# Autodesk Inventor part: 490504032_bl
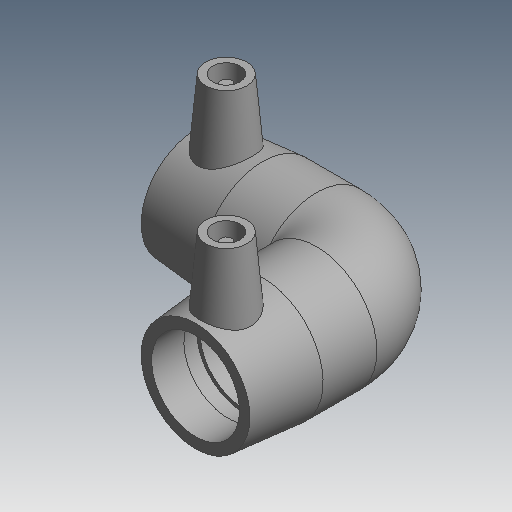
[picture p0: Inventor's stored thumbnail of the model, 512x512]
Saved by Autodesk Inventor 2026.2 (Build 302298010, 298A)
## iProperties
Created: 2017-06
Part Number: 490504032_bl
Material: Generic
Description: PLASSON 90° ELBOW 32
Document SubType Name: Modeling
Designer: KIM
Mass: 55.0731 g
Surface Area: 148.067 cm^2
Volume: 55.0731 cm^3
Density: 1 g/cm^3
Appearance: Default
Author: KIM
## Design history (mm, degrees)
derived "490504 -20-75.ipt"
feature "Solid1::490504 -20-75.ipt" dims "ScaleForDerivedMember" = 10
tag "TaggingFeature1"
body "Solid1"
other parameters: "d2" = 44 [user parameter], "d4" = 24.41176 [user parameter], "d5" = 39.6 [user parameter], "d8" = 168 deg [user parameter], "d10" = 17.6 [user parameter], "d11" = 5.86667 [user parameter], "d14" = 17.6296 [user parameter], "d18" = 32 [user parameter], "d19" = 3.52592 [user parameter], "d20" = 168 deg [user parameter], "d22" = 40.48 [user parameter], "d23" = 44 [user parameter], "d24" = 39.2656 [user parameter], "d29" = 43 [user parameter], "d30" = 15 [user parameter], "d31" = 49.8 [user parameter], "d34" = 5 deg [user parameter], "d35" = 15 [user parameter], "d39" = 5 deg [user parameter], "d41" = 4 [user parameter], "d42" = 14 [user parameter], "d43" = 0 [user parameter], "d45" = 4 [user parameter], "d46" = 14 [user parameter], "d47" = 0 [user parameter], "d49" = 32 [user parameter], "d50" = 27.2 [user parameter], "d51" = 17.6 [user parameter], "d52" = 44 [user parameter], "d54" = 90 deg [user parameter], "d65" = 32 [user parameter], "d67" = 45 deg [user parameter], "d71" = 90 deg [user parameter], "d75" = 2.2 [user parameter], "d82" = 45 deg [user parameter], "d83" = 44 [user parameter], "d84" = 39.6 [user parameter], "d87" = 90 deg [user parameter], "d90" = 44 [user parameter], "d91" = 0 [user parameter], "d92" = 44 [user parameter], "d93" = 0 [user parameter], "d94" = 90 deg [user parameter], "d101" = 3 [user parameter], "d102" = 0 [user parameter], "d103" = 3 [user parameter], "d104" = 0 [user parameter], "d105" = 12.76 [user parameter], "d106" = 3.19 [user parameter], "d110" = 24.2 [user parameter], "d111" = 83 [user parameter], "d112" = 83 [user parameter], "d113" = 83 [user parameter], "d114" = 83 [user parameter], "d_" = 32 [user parameter], "L_" = 83 [user parameter], "L_1" = 44 [user parameter], "D_" = 44 [user parameter], "A_" = 43 [user parameter], "d_2" = 12 [user parameter]
